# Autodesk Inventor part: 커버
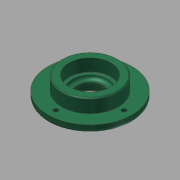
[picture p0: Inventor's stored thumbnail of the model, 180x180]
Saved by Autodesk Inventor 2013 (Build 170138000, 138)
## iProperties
Company: 한국ATC센터
Created: 2014-10
Part Number: 커버
Document SubType Name: Modeling
Designer: KYOUNG IL JANG
Density: 7.86 g/cm^3
Mass: 351.567 g
Surface Area: 161.165 cm^2
Volume: 44.7286 cm^3
Material: 강철, 연강
Author: KYOUNG IL JANG
Revision Number: 1
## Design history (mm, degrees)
sketch "스케치1"
  geometry: C1 r 40 at (0, 0); 1 further point
  constraints: 1 centre point, 1 coincident
  dimensions: "d0" = 80 diameter of C1
extrude "돌출1" new body sketch "스케치1" distance "d1" = 7; taper "d2" = 0 deg
sketch "스케치2"
  geometry: C1 r 27 at (0, 0); 1 further point
  constraints: 1 centre point, 1 coincident
  dimensions: "d3" = 54 diameter of C1
extrude "돌출2" join sketch "스케치2" distance "d4" = 13; taper "d5" = 0 deg
sketch "스케치3"
  geometry: C1 r 20 at (0, 0); 1 further point
  constraints: 1 centre point, 1 coincident
  dimensions: "d6" = 40 diameter of C1
extrude "돌출3" join sketch "스케치3" distance "d7" = 5; taper "d8" = 0 deg
hole "구멍1" diameter "d11" = 25; stored, may be unused: countersink angle "d15" = 90 deg, drill point angle "d17" = 118 deg; dims "d9" = 10, "d10" = 10, "d12" = 6, "d13" = 32, "d14" = 8.3, "d16" = 8
hole "구멍2" diameter "d20" = 34; stored, may be unused: countersink angle "d24" = 90 deg, drill point angle "d26" = 0 deg; dims "d18" = 10, "d19" = 10, "d21" = 6, "d22" = 40, "d23" = 12, "d25" = 3
fillet "모깎기2" dims "d34" = 3
fillet "모깎기1" dims "d27" = 0.3
chamfer "모따기1" distance "d28" = 1; stored, may be unused: second distance "d29" = 2, angle "d30" = 45 deg
chamfer "모따기2" distance "d31" = 1.2; stored, may be unused: second distance "d32" = 2, angle "d33" = 30 deg
sketch "스케치4" dims "d35" = 65
  geometry: 3 further points
  constraints: 2 horizontal alignment, 1 coincident, 2 other
hole "구멍3" sketch "스케치4" at (32.5, 0) diameter "d36" = 4.5; stored, may be unused: countersink angle "d40" = 90 deg, drill point angle "d42" = 118 deg; dims "d37" = 6, "d38" = 8, "d39" = 4.4, "d41" = 13
node "솔리드1"
pattern_circular "원형 패턴1" dims angle "d44" = 360 deg
